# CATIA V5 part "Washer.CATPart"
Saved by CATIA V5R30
Part number: washer
Bounding box of the stored display mesh (mm): x -24 to 24, y -23.825 to 23.825, z 0 to 3
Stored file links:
  D:\PROJECTS\CATIA V56R 2020\Resources\Parts File\c14_catia_v5_6r2020_prt\c14-catia-v5-6r2020-figr-14-26 & 27\Part & Asm\Washer.CATPart
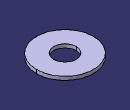
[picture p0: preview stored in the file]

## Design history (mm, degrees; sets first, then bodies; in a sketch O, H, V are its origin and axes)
Body1 (main body)
  Sketch1 on xy-plane, origin (0, 0, 0), H (1, 0, 0), V (0, 1, 0)
    circle A1 centre (0, 0) radius 24
    circle A2 centre (0, 0) radius 9.5
    radius A1 = 24
    radius A2 = 9.5
  Pad1: profile Sketch1, direction (0, 0, 1), length 3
